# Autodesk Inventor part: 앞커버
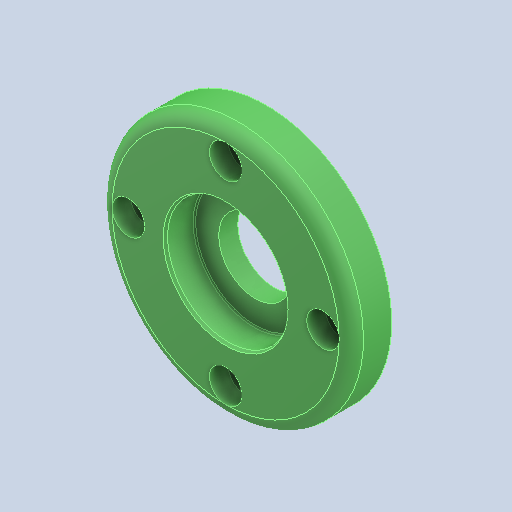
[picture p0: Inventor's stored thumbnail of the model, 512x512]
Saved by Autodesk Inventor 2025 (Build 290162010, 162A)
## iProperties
Created: 2024-07
Part Number: 앞커버
Material: 알루미늄 6061
Document SubType Name: Modeling
Designer: Admin
Density: 2.71 g/cm^3
Appearance: 기본값
Author: jhkim
Sending System: Autodesk Inventor 2025
Preprocessor: ST-DEVELOPER v20
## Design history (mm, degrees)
feature "솔리드1"
node "솔리드2"
